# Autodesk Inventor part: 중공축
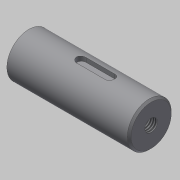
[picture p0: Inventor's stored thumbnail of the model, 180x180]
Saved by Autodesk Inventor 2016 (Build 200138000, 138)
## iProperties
Created: 2019-10
Part Number: 중공축
Material: 강철, 탄소
Document SubType Name: Modeling
Designer: mduedu
Density: 1 g/cm^3
Appearance: 기본값
Author: mduedu
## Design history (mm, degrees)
sketch "스케치1"
  geometry: L1 (0, 0)-(64, 0); L2 (64, 0)-(64, 11.5); L3 (64, 11.5)-(0, 11.5); L4 (0, 11.5)-(0, 0)
  constraints: 8 end point, 2 parallel, 1 horizontal, 1 perpendicular
  dimensions: "d0" = 64 distance of L2.end L3.end; "d2" = 23 diameter of L3 L1
revolve "회전1" sketch "스케치1" stored, may be unused: angle "d3" = 90 deg
hole "구멍1" diameter "d6" = 6.647; stored, may be unused: countersink angle "d10" = 90 deg, drill point angle "d12" = 118 deg; dims "d4" = 10, "d5" = 10, "d7" = 6, "d8" = 4, "d9" = 2, "d11" = 8
hole "구멍2" diameter "d15" = 13; stored, may be unused: countersink angle "d19" = 90 deg, drill point angle "d21" = 0 deg; dims "d13" = 10, "d14" = 10, "d16" = 6, "d17" = 15, "d18" = 20, "d20" = 32
sketch "스케치2"
  geometry: L1 (20, -7.5)-(20, -6.5) reference; L2 (20, -6.5)-(52, -6.5) reference; L3 (52, -6.5)-(52, -3.324) reference; L4 (52, -3.324)-(64, -3.324) reference; L5 (64, -3.324)-(64, -11.5) reference; L6 (64, -11.5)-(0, -11.5) reference; L7 (0, -11.5)-(0, -7.5) reference; L8 (0, -7.5)-(20, -7.5) reference; L9 (20, 6.5)-(20, 7.5) reference; L10 (20, 7.5)-(0, 7.5) reference; L11 (0, 7.5)-(0, 11.5) reference; L12 (0, 11.5)-(64, 11.5) reference; L13 (64, 11.5)-(64, 3.324) reference; L14 (64, 3.324)-(52, 3.324) reference; L15 (52, 3.324)-(52, 6.5) reference; L16 (52, 6.5)-(20, 6.5) reference; L17 (25, 11.5)-(45, 11.5); L18 (45, 11.5)-(45, 9); L19 (45, 9)-(25, 9); L20 (25, 9)-(25, 11.5); 1 further point
  constraints: 8 end point, 2 parallel, 1 horizontal, 1 perpendicular, 1 point on line
  dimensions: "d22" = 20 distance of L17.start L17.end; "d24" = 25 distance between parallel lines of L20 L11; "d25" = 2.5 distance of L17.end L18.end
extrude "돌출1" cut sketch "스케치2" stored distance "d26" = 5; taper "d27" = 0 deg
fillet "모깎기1"
fillet "모깎기2"
sketch "스케치3"
  geometry: 3 further points
  constraints: 2 vertical alignment, 1 other
hole "구멍3" sketch "스케치3" at (0, 7.5) diameter "d28" = 2.459; stored, may be unused: countersink angle "d32" = 90 deg, drill point angle "d34" = 118 deg; dims "d29" = 6, "d30" = 4, "d31" = 2, "d33" = 8
chamfer "모따기1" distance "d35" = 1; stored, may be unused: second distance "d36" = 2, angle "d37" = 45 deg
node "솔리드1"
node "절단 모서리 투영1"
